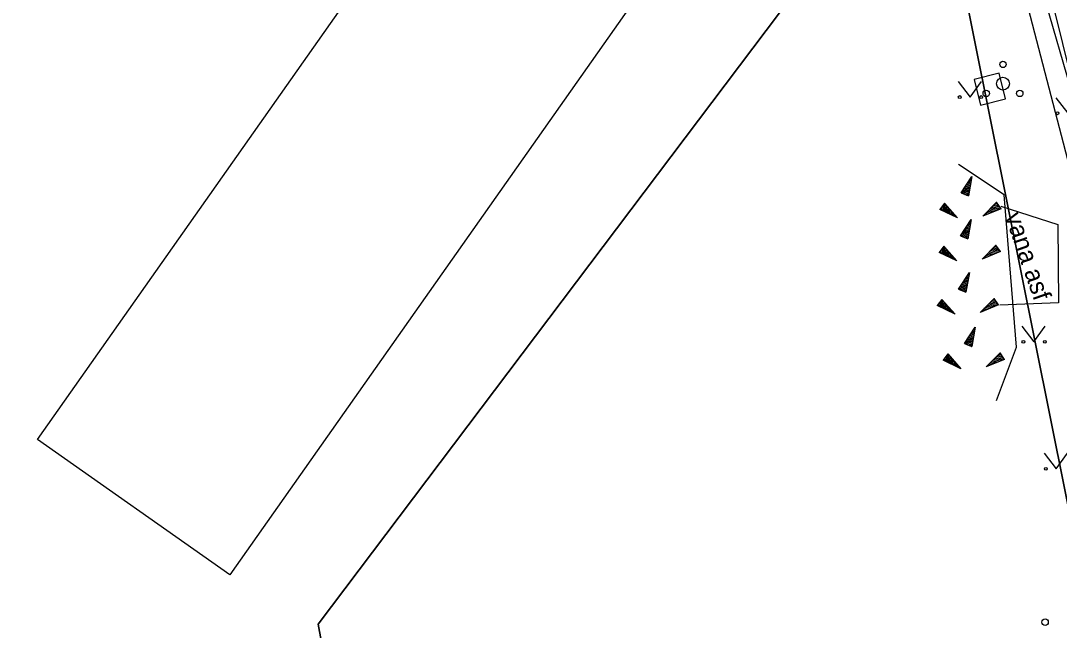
# Model space of a CAD drawing. Extents: x 554947 to 555436, y 6564938 to 6565792.
# Drawn here: x 555307.9 to 555348.19, y 6565480.81 to 6565504.44 of the extents above; entities that cross this region are included whole.
import ezdxf

# ---------------------------------------------------------------- set-up
doc = ezdxf.new("R2010")
doc.units = 0
for name, color, linetype in [('AED', 7, 'Continuous'), ('HALJASTUS', 7, 'Continuous'), ('Hoone Vare', 7, 'Continuous'), ('PIIR', 7, 'Continuous'), ('PR_SIDE', 7, 'Continuous'), ('PUU', 7, 'Continuous'), ('RELJEEF', 7, 'Continuous'), ('TEE', 7, 'Continuous')]:
    doc.layers.add(name, color=color, linetype=linetype)

msp = doc.modelspace()

# ---------------------------------------------------------------- linework, layer by layer
at = {"layer": 'AED'}
msp.add_lwpolyline([(555345.127, 6565501.175), (555346.107, 6565501.417), (555345.861, 6565502.412), (555344.881, 6565502.17)], close=True, dxfattribs=at)
at = {"layer": 'HALJASTUS'}
for p, q in [((555344.266, 6565502.094), (555344.729, 6565501.487)), ((555344.729, 6565501.487), (555345.175, 6565502.094)), ((555348.055, 6565501.461), (555348.518, 6565500.854)), ((555346.736, 6565492.596), (555347.199, 6565491.989)), ((555347.199, 6565491.989), (555347.645, 6565492.596)), ((555347.605, 6565487.672), (555348.068, 6565487.065)), ((555348.068, 6565487.065), (555348.514, 6565487.672))]:
    msp.add_line(p, q, dxfattribs=at)
for centre in [(555344.328, 6565501.487), (555345.157, 6565501.487), (555348.117, 6565500.854), (555346.798, 6565491.989), (555347.627, 6565491.989), (555347.667, 6565487.065)]:
    msp.add_circle(centre, 0.055, dxfattribs=at)
at = {"layer": 'Hoone Vare'}
msp.add_lwpolyline([(555316.008, 6565482.956), (555308.549, 6565488.207), (555330.789, 6565519.787), (555338.249, 6565514.537)], close=True, dxfattribs=at)
at = {"layer": 'PIIR'}
for points in [[(555153.01, 6565448.47), (555161.15, 6565451.45), (555173.66, 6565456.03), (555207.29, 6565506.14), (555287.77, 6565518.56), (555302.6, 6565539.71), (555343.14, 6565512.46), (555319.44, 6565481.04), (555323.07, 6565461.26), (555312.9, 6565433.84), (555316.84, 6565372.52), (555318.72, 6565342.57), (555320.51, 6565314.61), (555303.13, 6565302.54), (555208.78, 6565303.3), (555205.15, 6565297.11), (555200.72, 6565310.3), (555206.9, 6565339.44), (555221.23, 6565376.06), (555216.83, 6565392.35), (555207.22, 6565406.57)], [(555319.44, 6565481.04), (555343.14, 6565512.46), (555351.96, 6565468.55), (555367.06, 6565449.68), (555367.76, 6565374.28), (555361.76, 6565374.07), (555316.84, 6565372.52), (555312.9, 6565433.84), (555323.07, 6565461.26)]]:
    msp.add_lwpolyline(points, close=True, dxfattribs=at)
msp.add_lwpolyline([(555393.069, 6565443.872), (555367.06, 6565449.68), (555351.96, 6565468.55), (555343.14, 6565512.46), (555353.12, 6565523.87), (555358.8, 6565482.45), (555368.05, 6565461.11), (555393.069, 6565454.923)], dxfattribs=at)
at = {"layer": 'PR_SIDE'}
msp.add_lwpolyline([(555393.069, 6565447.47), (555392.755, 6565447.532), (555372.326, 6565450.448), (555366.015, 6565452.342), (555363.26, 6565453.626), (555360.292, 6565456.785), (555356.82, 6565461.856), (555353.746, 6565469.93), (555350.28, 6565487.806), (555348.596, 6565498.754), (555346.199, 6565508), (555346.027, 6565508.326), (555343.44, 6565510.968), (555340.158, 6565515.387), (555337.344, 6565518), (555330.24, 6565522.258), (555323.316, 6565526.613), (555319.055, 6565529.304), (555309.687, 6565535.684), (555303.916, 6565540.202)], dxfattribs=at)
at = {"layer": 'PUU'}
for centre, radius in [((555346.006, 6565502.752), 0.125), ((555346.006, 6565502.002), 0.25), ((555345.356, 6565501.627), 0.125), ((555346.656, 6565501.627), 0.125), ((555347.639, 6565481.12), 0.125)]:
    msp.add_circle(centre, radius, dxfattribs=at)
at = {"layer": 'RELJEEF'}
for p, q in [((555344.382, 6565497.766), (555344.802, 6565498.406)), ((555344.802, 6565498.406), (555344.662, 6565497.651)), ((555344.482, 6565497.916), (555344.732, 6565498.021)), ((555344.532, 6565497.991), (555344.657, 6565498.046)), ((555344.582, 6565498.066), (555344.752, 6565498.141)), ((555344.632, 6565498.141), (555344.762, 6565498.201)), ((555344.657, 6565498.046), (555344.742, 6565498.081)), ((555344.677, 6565498.216), (555344.777, 6565498.256)), ((555344.727, 6565498.291), (555344.787, 6565498.316)), ((555344.777, 6565498.366), (555344.797, 6565498.376)), ((555344.382, 6565497.766), (555344.707, 6565497.906)), ((555344.382, 6565497.766), (555344.662, 6565497.651)), ((555344.382, 6565497.766), (555344.382, 6565497.766)), ((555344.432, 6565497.841), (555344.717, 6565497.961)), ((555344.447, 6565497.741), (555344.697, 6565497.846)), ((555344.512, 6565497.711), (555344.687, 6565497.786)), ((555344.582, 6565497.686), (555344.677, 6565497.726)), ((555344.647, 6565497.661), (555344.662, 6565497.666)), ((555343.741, 6565497.366), (555343.556, 6565497.126)), ((555343.656, 6565497.256), (555343.681, 6565497.071)), ((555343.696, 6565497.311), (555343.731, 6565497.041)), ((555343.741, 6565497.366), (555344.246, 6565496.796)), ((555343.741, 6565497.366), (555343.786, 6565497.016)), ((555343.741, 6565497.366), (555343.741, 6565497.366)), ((555343.801, 6565497.301), (555343.841, 6565496.991)), ((555343.861, 6565497.231), (555343.896, 6565496.966)), ((555345.22, 6565496.861), (555345.76, 6565497.406)), ((555345.93, 6565497.156), (555345.58, 6565497.221)), ((555345.89, 6565497.211), (555345.625, 6565497.266)), ((555345.85, 6565497.271), (555345.665, 6565497.306)), ((555345.81, 6565497.331), (555345.71, 6565497.351)), ((555345.77, 6565497.391), (555345.75, 6565497.391)), ((555345.93, 6565497.156), (555345.76, 6565497.406)), ((555344.246, 6565496.796), (555343.556, 6565497.126)), ((555343.566, 6565497.141), (555343.571, 6565497.121)), ((555343.611, 6565497.196), (555343.626, 6565497.096)), ((555343.921, 6565497.166), (555343.936, 6565497.026)), ((555343.936, 6565497.026), (555343.951, 6565496.936)), ((555343.976, 6565497.096), (555344.006, 6565496.911)), ((555344.036, 6565497.031), (555344.056, 6565496.886)), ((555344.096, 6565496.961), (555344.111, 6565496.861)), ((555344.156, 6565496.896), (555344.166, 6565496.831)), ((555344.216, 6565496.826), (555344.221, 6565496.806)), ((555345.93, 6565497.156), (555345.22, 6565496.861)), ((555345.26, 6565496.876), (555345.245, 6565496.881)), ((555345.345, 6565496.911), (555345.285, 6565496.926)), ((555345.43, 6565496.946), (555345.325, 6565496.966)), ((555345.51, 6565496.981), (555345.37, 6565497.011)), ((555345.595, 6565497.016), (555345.41, 6565497.051)), ((555345.545, 6565497.076), (555345.455, 6565497.096)), ((555345.76, 6565497.086), (555345.495, 6565497.136)), ((555345.845, 6565497.121), (555345.54, 6565497.181)), ((555345.68, 6565497.051), (555345.545, 6565497.076)), ((555345.93, 6565497.156), (555345.93, 6565497.156)), ((555344.356, 6565496.101), (555344.776, 6565496.741)), ((555344.556, 6565496.401), (555344.726, 6565496.476)), ((555344.606, 6565496.476), (555344.736, 6565496.536)), ((555344.631, 6565496.381), (555344.716, 6565496.416)), ((555344.776, 6565496.741), (555344.636, 6565495.986)), ((555344.651, 6565496.551), (555344.751, 6565496.591)), ((555344.701, 6565496.626), (555344.761, 6565496.651)), ((555344.751, 6565496.701), (555344.771, 6565496.711)), ((555344.356, 6565496.101), (555344.681, 6565496.241)), ((555344.356, 6565496.101), (555344.636, 6565495.986)), ((555344.356, 6565496.101), (555344.356, 6565496.101)), ((555344.406, 6565496.176), (555344.691, 6565496.296)), ((555344.421, 6565496.076), (555344.671, 6565496.181)), ((555344.456, 6565496.251), (555344.706, 6565496.356)), ((555344.486, 6565496.046), (555344.661, 6565496.121)), ((555344.506, 6565496.326), (555344.631, 6565496.381)), ((555344.556, 6565496.021), (555344.651, 6565496.061)), ((555344.621, 6565495.996), (555344.636, 6565496.001)), ((555343.715, 6565495.7), (555343.53, 6565495.46)), ((555343.63, 6565495.59), (555343.655, 6565495.405)), ((555343.67, 6565495.645), (555343.705, 6565495.375)), ((555343.715, 6565495.7), (555344.22, 6565495.13)), ((555343.715, 6565495.7), (555343.76, 6565495.35)), ((555343.715, 6565495.7), (555343.715, 6565495.7)), ((555343.775, 6565495.635), (555343.815, 6565495.325)), ((555345.194, 6565495.195), (555345.734, 6565495.74)), ((555345.864, 6565495.545), (555345.599, 6565495.6)), ((555345.824, 6565495.605), (555345.639, 6565495.64)), ((555345.784, 6565495.665), (555345.684, 6565495.685)), ((555345.744, 6565495.725), (555345.724, 6565495.725)), ((555345.904, 6565495.49), (555345.734, 6565495.74)), ((555344.22, 6565495.13), (555343.53, 6565495.46)), ((555343.54, 6565495.475), (555343.545, 6565495.455)), ((555343.585, 6565495.53), (555343.6, 6565495.43)), ((555343.835, 6565495.565), (555343.87, 6565495.3)), ((555343.895, 6565495.5), (555343.91, 6565495.36)), ((555343.91, 6565495.36), (555343.925, 6565495.27)), ((555343.95, 6565495.43), (555343.98, 6565495.245)), ((555344.01, 6565495.365), (555344.03, 6565495.22)), ((555344.07, 6565495.295), (555344.085, 6565495.195)), ((555344.13, 6565495.23), (555344.14, 6565495.165)), ((555345.904, 6565495.49), (555345.194, 6565495.195)), ((555345.234, 6565495.21), (555345.219, 6565495.215)), ((555345.319, 6565495.245), (555345.259, 6565495.26)), ((555345.404, 6565495.28), (555345.299, 6565495.3)), ((555345.484, 6565495.315), (555345.344, 6565495.345)), ((555345.569, 6565495.35), (555345.384, 6565495.385)), ((555345.519, 6565495.41), (555345.429, 6565495.43)), ((555345.734, 6565495.42), (555345.469, 6565495.47)), ((555345.819, 6565495.455), (555345.514, 6565495.515)), ((555345.654, 6565495.385), (555345.519, 6565495.41)), ((555345.904, 6565495.49), (555345.554, 6565495.555)), ((555345.904, 6565495.49), (555345.904, 6565495.49)), ((555344.19, 6565495.16), (555344.195, 6565495.14)), ((555344.28, 6565494.038), (555344.7, 6565494.678)), ((555344.48, 6565494.338), (555344.65, 6565494.413)), ((555344.53, 6565494.413), (555344.66, 6565494.473)), ((555344.7, 6565494.678), (555344.56, 6565493.923)), ((555344.575, 6565494.488), (555344.675, 6565494.528)), ((555344.625, 6565494.563), (555344.685, 6565494.588)), ((555344.675, 6565494.638), (555344.695, 6565494.648)), ((555344.28, 6565494.038), (555344.605, 6565494.178)), ((555344.28, 6565494.038), (555344.56, 6565493.923)), ((555344.28, 6565494.038), (555344.28, 6565494.038)), ((555344.33, 6565494.113), (555344.615, 6565494.233)), ((555344.345, 6565494.013), (555344.595, 6565494.118)), ((555344.38, 6565494.188), (555344.63, 6565494.293)), ((555344.41, 6565493.983), (555344.585, 6565494.058)), ((555344.43, 6565494.263), (555344.555, 6565494.318)), ((555344.48, 6565493.958), (555344.575, 6565493.998)), ((555344.555, 6565494.318), (555344.64, 6565494.353)), ((555343.639, 6565493.637), (555343.454, 6565493.397)), ((555343.594, 6565493.582), (555343.629, 6565493.312)), ((555343.639, 6565493.637), (555344.144, 6565493.067)), ((555343.639, 6565493.637), (555343.684, 6565493.287)), ((555343.639, 6565493.637), (555343.639, 6565493.637)), ((555343.699, 6565493.572), (555343.739, 6565493.262)), ((555344.545, 6565493.933), (555344.56, 6565493.938)), ((555345.118, 6565493.132), (555345.658, 6565493.677)), ((555345.748, 6565493.542), (555345.563, 6565493.577)), ((555345.708, 6565493.602), (555345.608, 6565493.622)), ((555345.668, 6565493.662), (555345.648, 6565493.662)), ((555345.828, 6565493.427), (555345.658, 6565493.677)), ((555344.144, 6565493.067), (555343.454, 6565493.397)), ((555343.464, 6565493.412), (555343.469, 6565493.392)), ((555343.509, 6565493.467), (555343.524, 6565493.367)), ((555343.554, 6565493.527), (555343.579, 6565493.342)), ((555343.759, 6565493.502), (555343.794, 6565493.237)), ((555343.819, 6565493.437), (555343.834, 6565493.297)), ((555343.834, 6565493.297), (555343.849, 6565493.207)), ((555343.874, 6565493.367), (555343.904, 6565493.182)), ((555343.934, 6565493.302), (555343.954, 6565493.157)), ((555343.994, 6565493.232), (555344.009, 6565493.132)), ((555345.828, 6565493.427), (555345.118, 6565493.132)), ((555345.243, 6565493.182), (555345.183, 6565493.197)), ((555345.328, 6565493.217), (555345.223, 6565493.237)), ((555345.408, 6565493.252), (555345.268, 6565493.282)), ((555345.493, 6565493.287), (555345.308, 6565493.322)), ((555345.443, 6565493.347), (555345.353, 6565493.367)), ((555345.658, 6565493.357), (555345.393, 6565493.407)), ((555345.743, 6565493.392), (555345.438, 6565493.452)), ((555345.578, 6565493.322), (555345.443, 6565493.347)), ((555345.828, 6565493.427), (555345.478, 6565493.492)), ((555345.788, 6565493.482), (555345.523, 6565493.537)), ((555345.828, 6565493.427), (555345.828, 6565493.427)), ((555344.054, 6565493.167), (555344.064, 6565493.102)), ((555344.114, 6565493.097), (555344.119, 6565493.077)), ((555345.158, 6565493.147), (555345.143, 6565493.152)), ((555344.512, 6565491.922), (555344.932, 6565492.562)), ((555344.932, 6565492.562), (555344.792, 6565491.807)), ((555344.807, 6565492.372), (555344.907, 6565492.412)), ((555344.857, 6565492.447), (555344.917, 6565492.472)), ((555344.907, 6565492.522), (555344.927, 6565492.532)), ((555344.512, 6565491.922), (555344.837, 6565492.062)), ((555344.562, 6565491.997), (555344.847, 6565492.117)), ((555344.577, 6565491.897), (555344.827, 6565492.002)), ((555344.612, 6565492.072), (555344.862, 6565492.177)), ((555344.662, 6565492.147), (555344.787, 6565492.202)), ((555344.712, 6565492.222), (555344.882, 6565492.297)), ((555344.762, 6565492.297), (555344.892, 6565492.357)), ((555344.787, 6565492.202), (555344.872, 6565492.237)), ((555344.512, 6565491.922), (555344.792, 6565491.807)), ((555344.512, 6565491.922), (555344.512, 6565491.922)), ((555344.642, 6565491.867), (555344.817, 6565491.942)), ((555344.712, 6565491.842), (555344.807, 6565491.882)), ((555344.777, 6565491.817), (555344.792, 6565491.822)), ((555345.35, 6565491.016), (555345.89, 6565491.561)), ((555346.06, 6565491.311), (555345.89, 6565491.561)), ((555343.871, 6565491.521), (555343.686, 6565491.281)), ((555344.376, 6565490.951), (555343.686, 6565491.281)), ((555343.696, 6565491.296), (555343.701, 6565491.276)), ((555343.741, 6565491.351), (555343.756, 6565491.251)), ((555343.786, 6565491.411), (555343.811, 6565491.226)), ((555343.826, 6565491.466), (555343.861, 6565491.196)), ((555343.871, 6565491.521), (555344.376, 6565490.951)), ((555343.871, 6565491.521), (555343.916, 6565491.171)), ((555343.871, 6565491.521), (555343.871, 6565491.521)), ((555343.931, 6565491.456), (555343.971, 6565491.146)), ((555343.991, 6565491.386), (555344.026, 6565491.121)), ((555344.051, 6565491.321), (555344.066, 6565491.181)), ((555344.066, 6565491.181), (555344.081, 6565491.091)), ((555344.106, 6565491.251), (555344.136, 6565491.066)), ((555344.166, 6565491.186), (555344.186, 6565491.041)), ((555346.06, 6565491.311), (555345.35, 6565491.016)), ((555345.64, 6565491.136), (555345.5, 6565491.166)), ((555345.725, 6565491.171), (555345.54, 6565491.206)), ((555345.675, 6565491.231), (555345.585, 6565491.251)), ((555345.89, 6565491.241), (555345.625, 6565491.291)), ((555345.975, 6565491.276), (555345.67, 6565491.336)), ((555345.81, 6565491.206), (555345.675, 6565491.231)), ((555346.06, 6565491.311), (555345.71, 6565491.376)), ((555346.02, 6565491.366), (555345.755, 6565491.421)), ((555345.98, 6565491.426), (555345.795, 6565491.461)), ((555345.94, 6565491.486), (555345.84, 6565491.506)), ((555345.9, 6565491.546), (555345.88, 6565491.546)), ((555346.06, 6565491.311), (555346.06, 6565491.311)), ((555344.226, 6565491.116), (555344.241, 6565491.016)), ((555344.286, 6565491.051), (555344.296, 6565490.986)), ((555344.346, 6565490.981), (555344.351, 6565490.961)), ((555345.39, 6565491.031), (555345.375, 6565491.036)), ((555345.475, 6565491.066), (555345.415, 6565491.081)), ((555345.56, 6565491.101), (555345.455, 6565491.121))]:
    msp.add_line(p, q, dxfattribs=at)
msp.add_lwpolyline([(555345.748, 6565489.719), (555346.529, 6565491.782), (555346.048, 6565497.69), (555344.278, 6565498.871)], dxfattribs=at)
at = {"layer": 'TEE'}
for points in [[(555393.069, 6565448.493), (555392.904, 6565448.521), (555377.792, 6565450.52), (555372.547, 6565451.424), (555369.187, 6565452.37), (555366.443, 6565453.255), (555364.23, 6565454.662), (555361.13, 6565458.083), (555357.411, 6565463.749), (555354.693, 6565470.258), (555353.748, 6565473.64), (555352.733, 6565478.362), (555351.267, 6565487.961), (555349.516, 6565498.784), (555347.141, 6565508.358), (555345.332, 6565511.802), (555341.773, 6565516.752), (555338.53, 6565519.62), (555330.669, 6565524.333), (555325.029, 6565527.171), (555324.447, 6565527.997), (555320.204, 6565530.941)], [(555349.516, 6565498.784), (555346.789, 6565508.206), (555344.895, 6565511.389), (555341.304, 6565516.362), (555338.53, 6565519.62)], [(555345.917, 6565497.259), (555348.136, 6565496.536), (555348.165, 6565493.505), (555345.883, 6565493.414)]]:
    msp.add_lwpolyline(points, dxfattribs=at)

# ---------------------------------------------------------------- texts
msp.add_text('vana asf', height=0.7, rotation=289.1037, dxfattribs=at).set_placement((555346.069, 6565496.878))

doc.saveas('drawing.dxf')
